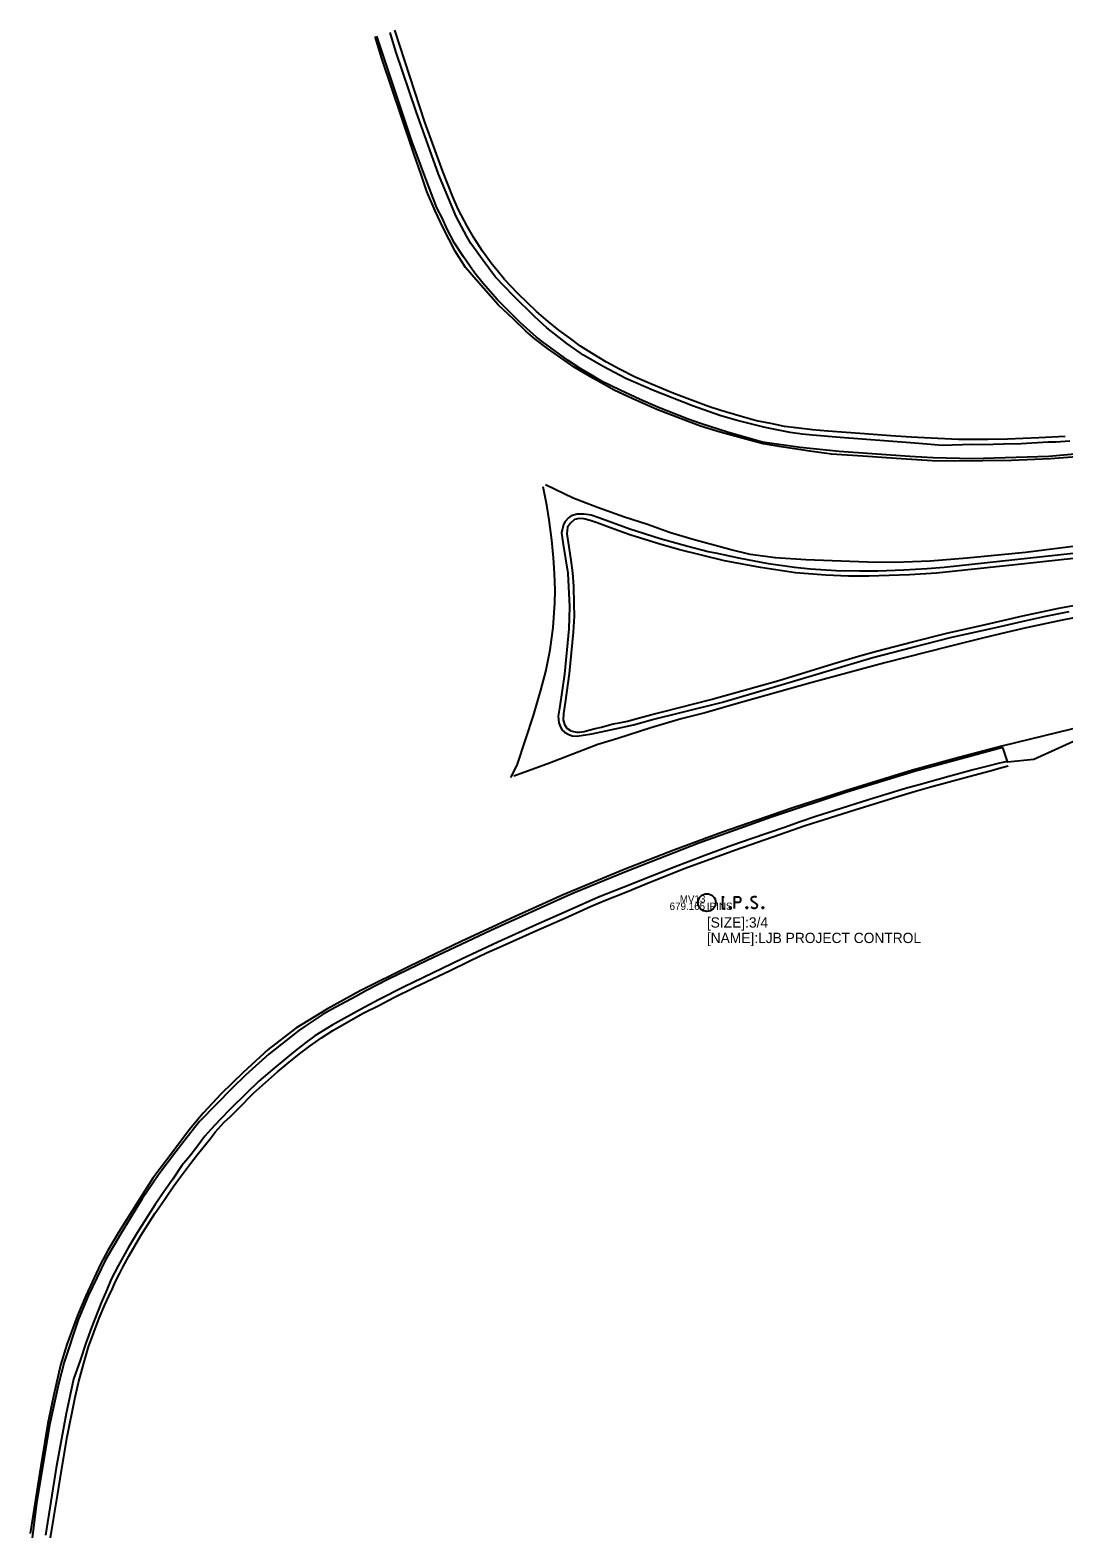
# Model space of a CAD drawing. Extents: x 1659932 to 1663108, y 619867 to 620611.
# Drawn here: x 1659932.4 to 1660072.9, y 620130.1 to 620335.2 of the extents above; entities that cross this region are included whole.
import ezdxf

# ---------------------------------------------------------------- set-up
doc = ezdxf.new("R2010")
doc.units = 0
for name, color, linetype in [('PM_X_Lane_Line', 7, 'Continuous'), ('PV_X_Curb', 7, 'Continuous'), ('PV_X_EOP', 7, 'Continuous'), ('RS_Raster1', 7, 'Continuous'), ('SV_P_Mon_Cells_Set_Text', 7, 'Continuous'), ('SV_X_Text_Comment', 7, 'Continuous'), ('SV_X_Text_Elevation', 7, 'Continuous'), ('SV_X_Text_Name', 7, 'Continuous')]:
    doc.layers.add(name, color=color, linetype=linetype)

msp = doc.modelspace()

# ---------------------------------------------------------------- linework, layer by layer
at = {"layer": 'PM_X_Lane_Line'}
for points in [[(1660074.65, 620277.16), (1660071.11, 620276.87), (1660068.96, 620276.77), (1660065.79, 620276.63), (1660061.91, 620276.6), (1660058.02, 620276.56), (1660055.02, 620276.6), (1660050.12, 620276.93), (1660045.61, 620277.25), (1660041.35, 620277.51), (1660038.4, 620277.93), (1660034.2, 620278.54), (1660032.05, 620278.89), (1660029.69, 620279.56), (1660026.21, 620280.51), (1660023.5, 620281.3), (1660020.9, 620282.3), (1660017.59, 620283.59), (1660014.29, 620285.01), (1660011.77, 620286.19), (1660008.95, 620287.77), (1660006.33, 620289.34), (1660002.7, 620291.88), (1660001.05, 620293.13), (1659999.78, 620294.23), (1659998.07, 620295.84), (1659996, 620297.83), (1659993.01, 620301.19), (1659991.54, 620302.89), (1659990.13, 620305.1), (1659988.51, 620308.27), (1659987.42, 620310.6), (1659986.32, 620313.2), (1659985.56, 620315.38), (1659984.55, 620318.37), (1659982.85, 620323.38), (1659980.19, 620331.3), (1659979.26, 620334.28)], [(1659997.7, 620233.54), (1659998.58, 620235.23), (1659999.72, 620238.64), (1660000.8, 620241.95), (1660001.79, 620245.41), (1660002.49, 620247.94), (1660003.06, 620250.91), (1660003.5, 620253.92), (1660003.72, 620257.24), (1660003.77, 620259), (1660003.67, 620261.27), (1660003.51, 620263.41), (1660003.3, 620265.82), (1660002.95, 620268.57), (1660002.63, 620270.57), (1660002.12, 620273.08)], [(1660076.7, 620265.28), (1660067.7, 620264.15), (1660059.77, 620263.34), (1660054.75, 620262.97), (1660049.95, 620262.79), (1660046.23, 620262.8), (1660037.86, 620263.12), (1660033.7, 620263.4), (1660030.25, 620263.87), (1660027.52, 620264.53), (1660022.33, 620265.96), (1660019.32, 620266.87), (1660016.31, 620267.92), (1660013.18, 620268.95), (1660009.51, 620270.23), (1660007.36, 620271.05), (1660006.19, 620271.54), (1660002.42, 620273.34)], [(1660077.9, 620255.93), (1660072.69, 620254.93), (1660067.8, 620253.88), (1660065.08, 620253.25), (1660061.85, 620252.47), (1660057.33, 620251.35), (1660048.59, 620249.14), (1660038.53, 620246.42), (1660028.03, 620243.47), (1660024.17, 620242.32), (1660020.88, 620241.5), (1660016.76, 620240.29), (1660012.28, 620238.83), (1660009.53, 620238.04), (1660002.97, 620235.48), (1659998.11, 620233.7)], [(1660081.39, 620241.92), (1660064.47, 620237.81), (1660058.63, 620236.27), (1660052.36, 620234.53), (1660043.08, 620231.66), (1660035.94, 620229.35), (1660026.52, 620226.12), (1660019.88, 620223.66), (1660013.15, 620221.01), (1660004.82, 620217.59), (1659998.31, 620214.63), (1659990.95, 620211.24), (1659983.89, 620207.83), (1659977.23, 620204.5), (1659972.79, 620202.07), (1659968.49, 620199.46), (1659964.74, 620196.55), (1659961.31, 620193.41), (1659958.31, 620190.53), (1659955.9, 620187.89), (1659954.02, 620185.65), (1659951.89, 620182.8), (1659949.06, 620179.05), (1659946.77, 620175.48), (1659944.37, 620171.64), (1659942.92, 620169.19), (1659941.93, 620167.35), (1659939.93, 620163.05), (1659938.79, 620160.35), (1659937.33, 620156.41), (1659936.5, 620153.61), (1659935.53, 620149.41), (1659934.75, 620145.72), (1659933.79, 620139.91), (1659932.36, 620130.72)]]:
    msp.add_lwpolyline(points, dxfattribs=at)
at = {"layer": 'PV_X_Curb'}
for points in [[(1660073.74, 620279.27), (1660071.83, 620279.13), (1660070.81, 620279.15), (1660067.11, 620278.92), (1660064.72, 620278.84), (1660061.87, 620278.78), (1660060.51, 620278.81), (1660056.36, 620278.68), (1660054.3, 620278.86), (1660052.05, 620279.02), (1660042.49, 620279.78), (1660038.73, 620280.08), (1660037.35, 620280.22), (1660035.72, 620280.44), (1660032.32, 620281.12), (1660028.5, 620282.08), (1660026.14, 620282.78), (1660022.43, 620284.06), (1660017.1, 620286.16), (1660013.38, 620287.79), (1660010.29, 620289.44), (1660007.61, 620290.97), (1660005.32, 620292.55), (1660002.63, 620294.7), (1660000.92, 620296.24), (1659998.07, 620299.02), (1659995.62, 620301.59), (1659993.94, 620303.82), (1659992.27, 620306.14), (1659991.74, 620307.1), (1659990.29, 620309.84), (1659987.9, 620315.57), (1659984.85, 620324.12), (1659982.1, 620332.27), (1659981.3, 620334.84)], [(1660073.12, 620279.9), (1660069.53, 620279.7), (1660065.25, 620279.56), (1660062.62, 620279.5), (1660060.57, 620279.48), (1660058.58, 620279.51), (1660055.77, 620279.62), (1660052.16, 620279.81), (1660049.38, 620279.98), (1660045.82, 620280.25), (1660040.85, 620280.61), (1660038.74, 620280.8), (1660036.52, 620281.06), (1660034.92, 620281.27), (1660033.1, 620281.67), (1660031.13, 620282.03), (1660028.9, 620282.66), (1660026.28, 620283.45), (1660024.59, 620284), (1660021.68, 620285.05), (1660019.89, 620285.73), (1660016.87, 620287.01), (1660014.64, 620287.98), (1660012.48, 620289.06), (1660010.75, 620290.01), (1660008.66, 620291.29), (1660007.21, 620292.2), (1660005.68, 620293.3), (1660004.26, 620294.38), (1660002.82, 620295.52), (1660001.19, 620296.91), (1659998.66, 620299.36), (1659996.87, 620301.25), (1659995.91, 620302.41), (1659995.18, 620303.31), (1659993.86, 620305.12), (1659992.64, 620306.99), (1659991.8, 620308.49), (1659990.58, 620310.84), (1659989.82, 620312.51), (1659988.49, 620315.93), (1659986.01, 620322.66), (1659981.94, 620335.16)], [(1660075.89, 620264.19), (1660066.28, 620263.11), (1660056.63, 620262.11), (1660054.34, 620261.9), (1660051.16, 620261.72), (1660047.65, 620261.6), (1660045.13, 620261.58), (1660041.98, 620261.64), (1660038.45, 620261.85), (1660036.28, 620262.1), (1660032.78, 620262.6), (1660028.73, 620263.37), (1660025.61, 620264.04), (1660024.55, 620264.23), (1660021.77, 620264.94), (1660018.02, 620265.98), (1660013.9, 620267.3), (1660009.68, 620268.83), (1660008.65, 620269.22), (1660007.7, 620269.34), (1660006.74, 620269.36), (1660005.93, 620269.12), (1660005.58, 620268.83), (1660005.09, 620268.36), (1660004.89, 620267.92), (1660004.63, 620266.81), (1660004.84, 620265.21), (1660005.46, 620261.33), (1660005.69, 620256.73), (1660005.59, 620253.75), (1660005.01, 620247.6), (1660004.37, 620243.23), (1660004.17, 620241.88), (1660004.25, 620240.98), (1660004.41, 620240.49), (1660004.64, 620240.02), (1660005.02, 620239.71), (1660005.51, 620239.42), (1660006.05, 620239.21), (1660006.71, 620239.14), (1660008.74, 620239.46), (1660011.92, 620240.17), (1660014.42, 620240.7), (1660016.98, 620241.43), (1660020.85, 620242.37), (1660026.49, 620243.79), (1660033.59, 620245.85), (1660042.71, 620248.58), (1660046.93, 620249.87), (1660052.21, 620251.23), (1660057.67, 620252.6), (1660063.68, 620253.91), (1660067.21, 620254.76), (1660070.47, 620255.46), (1660073.63, 620256.1)], [(1660075.9, 620263.48), (1660066.29, 620262.44), (1660055.6, 620261.33), (1660051.95, 620261.07), (1660046.42, 620260.89), (1660043.66, 620260.91), (1660040.56, 620261.03), (1660036.43, 620261.36), (1660031.69, 620262.11), (1660026.77, 620262.99), (1660020.5, 620264.55), (1660017.83, 620265.31), (1660013.91, 620266.54), (1660011.26, 620267.5), (1660009.44, 620268.17), (1660008.49, 620268.49), (1660007.67, 620268.69), (1660007.03, 620268.76), (1660006.36, 620268.6), (1660005.82, 620268.14), (1660005.45, 620267.57), (1660005.34, 620266.67), (1660005.54, 620265.49), (1660005.87, 620263.09), (1660006.09, 620261.37), (1660006.25, 620259.54), (1660006.31, 620257.12), (1660006.33, 620255.45), (1660006.18, 620253.3), (1660005.66, 620247.66), (1660005.12, 620243.72), (1660004.9, 620242.23), (1660004.86, 620241.39), (1660005.02, 620240.75), (1660005.34, 620240.25), (1660005.83, 620239.91), (1660005.9, 620239.9)], [(1660005.9, 620239.9), (1660006.25, 620239.77), (1660006.68, 620239.68), (1660007.05, 620239.71), (1660007.68, 620239.79), (1660008.31, 620239.96), (1660009.17, 620240.19), (1660010.03, 620240.39), (1660010.81, 620240.61), (1660011.65, 620240.81), (1660012.46, 620240.95), (1660013.6, 620241.21), (1660015.22, 620241.65), (1660016.89, 620242.09), (1660018.54, 620242.49), (1660024.92, 620244.13), (1660034.18, 620246.72), (1660041.51, 620249), (1660044.98, 620250.04), (1660047.47, 620250.71), (1660052.34, 620251.97), (1660057.01, 620253.14), (1660062.25, 620254.32), (1660067.33, 620255.5), (1660072.24, 620256.54), (1660075.73, 620257.21)], [(1660065.24, 620235.73), (1660064.18, 620235.46), (1660062.41, 620235.02), (1660060.61, 620234.59), (1660057.3, 620233.67), (1660053.25, 620232.54), (1660051.4, 620232.02), (1660048.7, 620231.21), (1660046.35, 620230.5), (1660041.8, 620229.06), (1660039.2, 620228.22), (1660037.07, 620227.49), (1660034.93, 620226.75), (1660030.39, 620225.21), (1660027.89, 620224.32), (1660024.09, 620222.91), (1660019.84, 620221.3), (1660016.97, 620220.17), (1660012.98, 620218.59), (1660009.63, 620217.24), (1660005.8, 620215.55), (1660001.18, 620213.49), (1659995.94, 620211.13), (1659991.03, 620208.82), (1659983.22, 620205.06), (1659979.71, 620203.29), (1659977.27, 620201.99), (1659975.04, 620200.78), (1659973.43, 620199.86), (1659971.09, 620198.4), (1659969.85, 620197.5), (1659968.15, 620196.16), (1659965.53, 620194.01), (1659963.47, 620192.23), (1659961.72, 620190.57), (1659959.61, 620188.47), (1659958.21, 620187.01), (1659956.94, 620185.68), (1659956.11, 620184.78), (1659955.11, 620183.4), (1659954.08, 620182.03), (1659952.97, 620180.78), (1659951.77, 620178.91), (1659950.54, 620177.18), (1659949.35, 620175.46), (1659946.89, 620171.6), (1659945.69, 620169.59), (1659944.31, 620167.11), (1659943.36, 620165.32), (1659942.76, 620163.85), (1659942.03, 620162.11), (1659940.68, 620158.76), (1659939.92, 620156.59), (1659939.22, 620154.38), (1659938.25, 620151.7), (1659937.79, 620149.57), (1659937.26, 620147.06), (1659935.88, 620139.64), (1659934.43, 620130.52)], [(1659935.11, 620130.15), (1659935.54, 620132.62), (1659936.06, 620135.91), (1659936.64, 620139.28), (1659937.41, 620143.86), (1659938.42, 620149.06), (1659938.93, 620151.24), (1659939.67, 620153.87), (1659940.31, 620156.1), (1659941.01, 620158.08), (1659941.75, 620160.02), (1659942.53, 620161.82), (1659943.06, 620162.99), (1659943.6, 620164.15), (1659943.9, 620164.9), (1659944.54, 620166.15), (1659944.98, 620166.96), (1659945.76, 620168.43), (1659946.6, 620169.85), (1659947.42, 620171.23), (1659949.31, 620174.22), (1659950.1, 620175.34), (1659951.82, 620177.89), (1659952.54, 620178.88), (1659954.16, 620181.03), (1659955.08, 620182.23), (1659956.82, 620184.41), (1659957.5, 620185.28), (1659958.75, 620186.68), (1659959.58, 620187.45), (1659960.69, 620188.54), (1659962.72, 620190.59), (1659964.34, 620192.05), (1659965.98, 620193.52), (1659967.32, 620194.61), (1659969, 620195.94), (1659970.45, 620197.04), (1659971.96, 620198.15), (1659973.53, 620199.13), (1659975.31, 620200.17), (1659977.66, 620201.48), (1659979.84, 620202.57), (1659981.81, 620203.61), (1659984.57, 620204.97), (1659989.46, 620207.3), (1659992.14, 620208.62), (1659994.42, 620209.67), (1659996.19, 620210.45), (1660001.11, 620212.68), (1660005.07, 620214.4), (1660008.57, 620215.98), (1660010.39, 620216.76), (1660013.58, 620218.01), (1660016.54, 620219.24), (1660021.42, 620221.18), (1660028.29, 620223.68), (1660034.24, 620225.76), (1660037.76, 620226.99), (1660039.45, 620227.57), (1660044.52, 620229.14), (1660050.92, 620231.11), (1660052.77, 620231.69), (1660054.67, 620232.23), (1660059.49, 620233.53), (1660063.39, 620234.58), (1660064.15, 620234.78), (1660065.37, 620235.1)]]:
    msp.add_lwpolyline(points, dxfattribs=at)
at = {"layer": 'PV_X_EOP'}
for points in [[(1660080.43, 620278.03), (1660070.88, 620277.18), (1660060.49, 620276.88), (1660055.17, 620277.02), (1660052, 620277.2), (1660042.38, 620277.87), (1660037.07, 620278.4), (1660031.95, 620279.13), (1660027.32, 620280.45), (1660023.51, 620281.69), (1660021.84, 620282.26), (1660017.79, 620283.83), (1660015.33, 620284.92), (1660012.57, 620286.2), (1660010.07, 620287.41), (1660008.85, 620288.17), (1660007.26, 620289.11), (1660005.5, 620290.24), (1660004.34, 620291.08), (1660001.98, 620292.81), (1660001.21, 620293.41), (1660000.33, 620294.18), (1659998.98, 620295.4), (1659997, 620297.39), (1659995.92, 620298.48), (1659993.98, 620300.72), (1659992.82, 620302.1), (1659992.08, 620303.15), (1659991.3, 620304.32), (1659990.08, 620306.19), (1659989.01, 620308.2), (1659988.42, 620309.53), (1659987.67, 620310.99), (1659986.15, 620314.92), (1659984.24, 620320.07), (1659983.12, 620323.47), (1659979.52, 620334.36)], [(1660075.63, 620239.07), (1660068.83, 620235.99), (1660065.28, 620235.61), (1660065.24, 620235.73), (1660064.64, 620237.59)], [(1660064.64, 620237.59), (1660060.15, 620236.39), (1660052.75, 620234.39), (1660043.41, 620231.53), (1660033.17, 620228.13), (1660023.27, 620224.61), (1660013.45, 620220.76), (1660006.47, 620217.9), (1660005.03, 620217.27), (1659994.99, 620212.73), (1659988.55, 620209.71), (1659986.43, 620208.7), (1659980.99, 620206.05), (1659978.1, 620204.56), (1659976.63, 620203.76), (1659973.32, 620202), (1659972.07, 620201.26), (1659969.76, 620199.73), (1659968.88, 620199.14), (1659964.83, 620195.9), (1659961.63, 620193.06), (1659959.87, 620191.34), (1659955.37, 620186.73), (1659953.69, 620184.64), (1659952.17, 620182.65), (1659949.91, 620179.64), (1659947.6, 620176.22), (1659944.58, 620171.33), (1659942.6, 620167.94), (1659940.25, 620163.06), (1659938.87, 620159.77), (1659936.96, 620154.02), (1659936.2, 620151.02), (1659934.99, 620145.47), (1659933.21, 620134.82), (1659932.61, 620130.14)]]:
    msp.add_lwpolyline(points, dxfattribs=at)
at = {"layer": 'RS_Raster1'}
for points in [[(1660026.4, 620217.32), (1660026.75, 620217.32)], [(1660026.4, 620215.72), (1660026.75, 620215.72)], [(1660026.57, 620215.72), (1660026.57, 620217.32)], [(1660027.53, 620215.94), (1660027.59, 620215.94), (1660027.62, 620215.91), (1660027.65, 620215.86), (1660027.65, 620215.8), (1660027.62, 620215.75), (1660027.59, 620215.72), (1660027.53, 620215.72), (1660027.5, 620215.75), (1660027.47, 620215.8), (1660027.47, 620215.86), (1660027.5, 620215.91), (1660027.53, 620215.94)], [(1660028.14, 620215.72), (1660028.14, 620217.32), (1660028.67, 620217.32), (1660028.72, 620217.31), (1660028.8, 620217.28), (1660028.83, 620217.26), (1660028.87, 620217.23), (1660028.91, 620217.17), (1660028.94, 620217.11), (1660028.97, 620217.01), (1660028.97, 620216.86), (1660028.96, 620216.81), (1660028.93, 620216.73), (1660028.89, 620216.64), (1660028.85, 620216.6), (1660028.81, 620216.58), (1660028.76, 620216.55), (1660028.67, 620216.54), (1660028.14, 620216.54)], [(1660029.78, 620215.94), (1660029.84, 620215.94), (1660029.87, 620215.91), (1660029.9, 620215.86), (1660029.9, 620215.8), (1660029.87, 620215.75), (1660029.84, 620215.72), (1660029.78, 620215.72), (1660029.75, 620215.75), (1660029.72, 620215.8), (1660029.72, 620215.86), (1660029.75, 620215.91), (1660029.78, 620215.94)], [(1660031.15, 620217.21), (1660031.13, 620217.23), (1660031.09, 620217.26), (1660030.99, 620217.3), (1660030.87, 620217.32), (1660030.79, 620217.32), (1660030.75, 620217.32), (1660030.61, 620217.28), (1660030.49, 620217.21), (1660030.41, 620217.11), (1660030.39, 620217.01), (1660030.39, 620216.93), (1660030.41, 620216.83), (1660030.5, 620216.74), (1660031.1, 620216.37), (1660031.16, 620216.31), (1660031.18, 620216.26), (1660031.2, 620216.19), (1660031.2, 620216.11), (1660031.19, 620216.04), (1660031.18, 620215.99), (1660031.16, 620215.92), (1660031.14, 620215.87), (1660031.12, 620215.84), (1660031.08, 620215.8), (1660031.05, 620215.77), (1660031.01, 620215.75), (1660030.97, 620215.74), (1660030.87, 620215.72), (1660030.72, 620215.72), (1660030.62, 620215.75), (1660030.48, 620215.84), (1660030.39, 620215.91)], [(1660031.96, 620215.94), (1660032.02, 620215.94), (1660032.05, 620215.91), (1660032.09, 620215.86), (1660032.09, 620215.8), (1660032.05, 620215.75), (1660032.02, 620215.72), (1660031.96, 620215.72), (1660031.93, 620215.75), (1660031.9, 620215.8), (1660031.9, 620215.86), (1660031.93, 620215.91), (1660031.96, 620215.94)]]:
    msp.add_lwpolyline(points, dxfattribs=at)
msp.add_circle((1660024.38, 620216.52), 1.2, dxfattribs=at)

# ---------------------------------------------------------------- texts
at = {"layer": 'SV_P_Mon_Cells_Set_Text'}
for s, p in [('[SIZE]:3/4', (1660024.38, 620213.12)), ('[NAME]:LJB PROJECT CONTROL', (1660024.38, 620211.02))]:
    msp.add_text(s, height=1.4, dxfattribs=at).set_placement(p)
at = {"layer": 'SV_X_Text_Comment'}
msp.add_text('IPINS', height=1, dxfattribs=at).set_placement((1660024.38, 620215.52))
at = {"layer": 'SV_X_Text_Elevation'}
msp.add_text('679.165', height=1, dxfattribs=at).set_placement((1660019.31, 620215.52))
at = {"layer": 'SV_X_Text_Name'}
msp.add_text('MV13', height=1, dxfattribs=at).set_placement((1660020.69, 620216.52))

doc.saveas('drawing.dxf')
